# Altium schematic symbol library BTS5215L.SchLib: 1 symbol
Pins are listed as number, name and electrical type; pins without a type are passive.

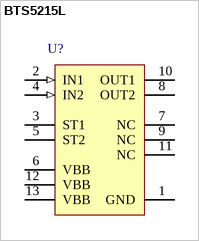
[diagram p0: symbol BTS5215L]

## BTS5215L
designator U?
Smart High-Side Power Switch, 2 Channels, 2.1 A Load Current, -40 to 150 degC, PG-DSO-12-9, Reel, Green; Manufacturer: Infineon; PartNumber: BTS5215L; Channels: 2; Green: TRUE; Group: Automotive Qualified; Load Current (typ): 2.1 A; Ptot (max): 3.1 W; Recommended Operating Voltage Max.: 40 V; Recommended Operating Voltage Min.: 5.5 V; RON @ 25degreesC: 90 mOhm; RON(max) @ 150degreesC: 180 mOhm; toff (max): 270 us; ton (max): 250 us
footprint INF-PG-DSO-12-9_N (SOP, 12-Leads, Body 7.5x6.4mm, Pitch 1mm, Thermal Pad 7.9x4.3mm, IPC Medium Density)
footprint INF-PG-DSO-12-9_L (SOP, 12-Leads, Body 7.5x6.4mm, Pitch 1mm, Thermal Pad 7.9x4.3mm, IPC High Density)
footprint INF-PG-DSO-12-9_M (SOP, 12-Leads, Body 7.5x6.4mm, Pitch 1mm, Thermal Pad 7.9x4.3mm, IPC Low Density)
pins: 1 GND (power) "Ground of chip", 2 IN1 (in) "Input 1,2 activates channel 1,2 in case of logic high signal", 3 ST1 (oc) "Diagnostic feedback 1 & 2 of channel 1,2 open drain, low on failure", 4 IN2 (in) "Input 1,2 activates channel 1,2 in case of logic high signal", 5 ST2 (oc) "Diagnostic feedback 1 & 2 of channel 1,2 open drain, low on failure", 6 VBB (power) "Positive power supply voltage. Design the wiring for the simultaneous max. short circuit currents from channel 1 to 2 and also for low thermal resistance", 7 NC "Not Connected", 8 OUT2 (power) "Output 1,2 protected high-side power output of channel 1 and 2. Design the wiring for the max. short circuit current", 9 NC "Not Connected", 10 OUT1 (power) "Output 1,2 protected high-side power output of channel 1 and 2. Design the wiring for the max. short circuit current", 11 NC "Not Connected", 12 VBB (power) "Positive power supply voltage. Design the wiring for the simultaneous max. short circuit currents from channel 1 to 2 and also for low thermal resistance", 13 VBB (power) "Positive power supply voltage. Design the wiring for the simultaneous max. short circuit currents from channel 1 to 2 and also for low thermal resistance"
